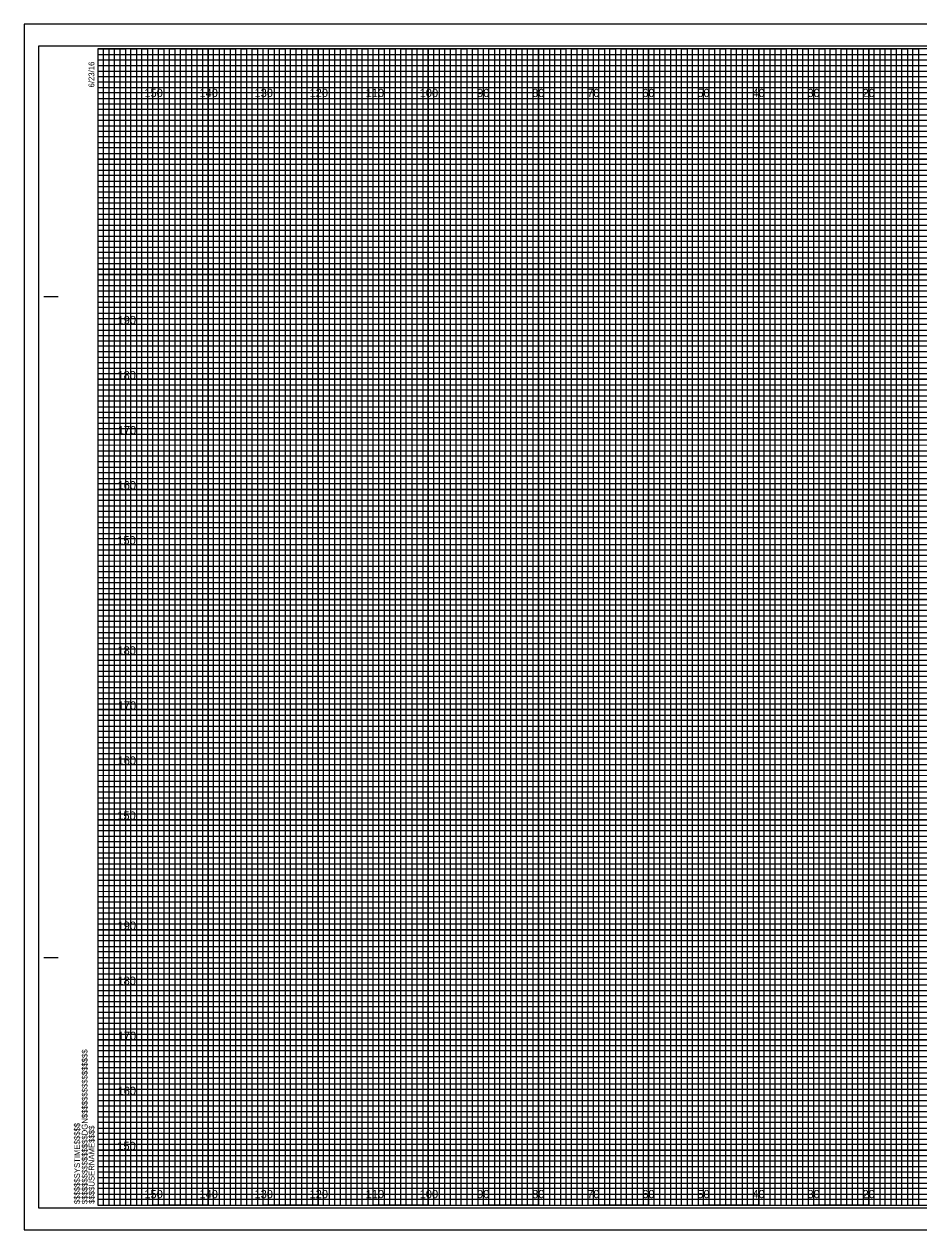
# Model space of a CAD drawing. Extents: x -13 to 323, y -5 to 434.
# Drawn here: x -13.4 to 149.1, y 215.5 to 434.5 of the extents above; entities that cross this region are included whole.
import ezdxf

# ---------------------------------------------------------------- set-up
doc = ezdxf.new("R2010")
doc.units = 0
for name, color, linetype in [('Exist Cross Section Cell', 7, 'Continuous'), ('Exist XS Center Line Elevation Label', 7, 'Continuous'), ('Exist XS Ground Line', 7, 'Continuous'), ('Prop CMT Pvmt Course 1', 7, 'Continuous'), ('Prop CMT Pvmt Course 2', 7, 'Continuous'), ('Prop CMT Pvmt Course 3', 7, 'Continuous'), ('Prop CMT Shld Paved Course 1', 7, 'Continuous'), ('Prop CMT Shld Paved Course 2', 7, 'Continuous'), ('Prop CMT Subgrade Earthwork', 7, 'Continuous'), ('Prop XS Ditch Standard Text', 7, 'Continuous'), ('Scratch_Level_0', 7, 'Continuous')]:
    doc.layers.add(name, color=color, linetype=linetype)

msp = doc.modelspace()

# ---------------------------------------------------------------- linework, layer by layer
at = {"layer": 'Exist XS Center Line Elevation Label'}
for points in [[(0, 430), (5, 430), (5, 220), (15, 220), (15, 430), (25, 430), (25, 220), (35, 220), (35, 430), (45, 430), (45, 220), (55, 220), (55, 430), (65, 430), (65, 220), (75, 220), (75, 430), (85, 430), (85, 220), (95, 220), (95, 430), (105, 430), (105, 220), (115, 220), (115, 430), (125, 430), (125, 220), (135, 220), (135, 430), (145, 430), (145, 220), (155, 220)], [(0, 425), (275, 425)], [(0, 405), (320, 405), (320, 415), (0, 415)], [(0, 385), (320, 385), (320, 395), (0, 395)], [(0, 365), (320, 365), (320, 375), (0, 375)], [(0, 345), (320, 345), (320, 355), (0, 355)], [(0, 325), (320, 325), (320, 335), (0, 335)], [(0, 305), (320, 305), (320, 315), (0, 315)], [(0, 285), (320, 285), (320, 295), (0, 295)], [(0, 265), (320, 265), (320, 275), (0, 275)], [(0, 245), (320, 245), (320, 255), (0, 255)], [(0, 225), (320, 225), (320, 235), (0, 235)]]:
    msp.add_lwpolyline(points, dxfattribs=at)
at = {"layer": 'Exist XS Ground Line'}
for p, q in [((10, 430), (0, 430)), ((10, 220), (10, 430)), ((30, 430), (20, 430)), ((20, 430), (20, 220)), ((30, 220), (30, 430)), ((50, 430), (40, 430)), ((40, 430), (40, 220)), ((50, 220), (50, 430)), ((70, 430), (60, 430)), ((60, 430), (60, 220)), ((70, 220), (70, 430)), ((90, 430), (80, 430)), ((80, 430), (80, 220)), ((90, 220), (90, 430)), ((110, 430), (100, 430)), ((100, 430), (100, 220)), ((110, 220), (110, 430)), ((130, 430), (120, 430)), ((120, 430), (120, 220)), ((130, 220), (130, 430)), ((150, 430), (140, 430)), ((140, 430), (140, 220)), ((20, 220), (10, 220)), ((40, 220), (30, 220)), ((60, 220), (50, 220)), ((80, 220), (70, 220)), ((100, 220), (90, 220)), ((120, 220), (110, 220)), ((140, 220), (130, 220))]:
    msp.add_line(p, q, dxfattribs=at)
for points in [[(0, 420), (320, 420), (320, 410), (0, 410)], [(0, 400), (320, 400), (320, 390), (0, 390)], [(0, 380), (320, 380), (320, 370), (0, 370)], [(0, 360), (320, 360), (320, 350), (0, 350)], [(0, 340), (320, 340), (320, 330), (0, 330)], [(0, 320), (320, 320), (320, 310), (0, 310)], [(0, 300), (320, 300), (320, 290), (0, 290)], [(0, 280), (320, 280), (320, 270), (0, 270)], [(0, 260), (320, 260), (320, 250), (0, 250)], [(0, 240), (320, 240), (320, 230), (0, 230)]]:
    msp.add_lwpolyline(points, dxfattribs=at)
at = {"layer": 'Prop CMT Pvmt Course 1'}
for p, q in [((323.3, 434.5), (-13.4, 434.5)), ((-13.4, 434.5), (-13.4, 215.5)), ((-13.4, 215.5), (323.3, 215.5))]:
    msp.add_line(p, q, dxfattribs=at)
at = {"layer": 'Prop CMT Pvmt Course 2'}
msp.add_lwpolyline([(-13.4, 215.5), (323.3, 215.5), (323.3, 434.5), (-13.4, 434.5)], close=True, dxfattribs=at)
at = {"layer": 'Prop CMT Pvmt Course 3'}
msp.add_lwpolyline([(-10.8, 219.5), (322.4, 219.5), (322.4, 430.5), (-10.8, 430.5)], close=True, dxfattribs=at)
at = {"layer": 'Prop CMT Shld Paved Course 1'}
for p, q in [((-9.8, 385), (-7.3, 385)), ((-9.7, 385), (-7.2, 385)), ((-9.8, 265), (-7.3, 265)), ((-9.7, 265), (-7.2, 265)), ((0, 220), (0, 220)), ((0, 220), (0, 220)), ((0, 220), (0, 220)), ((0, 220), (0, 220)), ((0, 220), (0, 220)), ((0, 220), (0, 220)), ((0, 220), (0, 220))]:
    msp.add_line(p, q, dxfattribs=at)
msp.add_lwpolyline([(320, 430), (0, 430), (0, 220), (320, 220)], close=True, dxfattribs=at)
at = {"layer": 'Prop CMT Shld Paved Course 2'}
for points in [[(0, 220), (1, 220), (1, 430), (2, 430), (2, 220)], [(2, 220), (3, 220), (3, 430), (4, 430), (4, 220)], [(5, 220), (6, 220), (6, 430), (7, 430), (7, 220)], [(7, 220), (8, 220), (8, 430), (9, 430), (9, 220)], [(10, 220), (11, 220), (11, 430), (12, 430), (12, 220)], [(12, 220), (13, 220), (13, 430), (14, 430), (14, 220)], [(15, 220), (16, 220), (16, 430), (17, 430), (17, 220)], [(17, 220), (18, 220), (18, 430), (19, 430), (19, 220)], [(20, 220), (21, 220), (21, 430), (22, 430), (22, 220)], [(22, 220), (23, 220), (23, 430), (24, 430), (24, 220)], [(25, 220), (26, 220), (26, 430), (27, 430), (27, 220)], [(27, 220), (28, 220), (28, 430), (29, 430), (29, 220)], [(30, 220), (31, 220), (31, 430), (32, 430), (32, 220)], [(32, 220), (33, 220), (33, 430), (34, 430), (34, 220)], [(35, 220), (36, 220), (36, 430), (37, 430), (37, 220)], [(37, 220), (38, 220), (38, 430), (39, 430), (39, 220)], [(40, 220), (41, 220), (41, 430), (42, 430), (42, 220)], [(42, 220), (43, 220), (43, 430), (44, 430), (44, 220)], [(45, 220), (46, 220), (46, 430), (47, 430), (47, 220)], [(47, 220), (48, 220), (48, 430), (49, 430), (49, 220)], [(50, 220), (51, 220), (51, 430), (52, 430), (52, 220)], [(52, 220), (53, 220), (53, 430), (54, 430), (54, 220)], [(55, 220), (56, 220), (56, 430), (57, 430), (57, 220)], [(57, 220), (58, 220), (58, 430), (59, 430), (59, 220)], [(60, 220), (61, 220), (61, 430), (62, 430), (62, 220)], [(62, 220), (63, 220), (63, 430), (64, 430), (64, 220)], [(65, 220), (66, 220), (66, 430), (67, 430), (67, 220)], [(67, 220), (68, 220), (68, 430), (69, 430), (69, 220)], [(70, 220), (71, 220), (71, 430), (72, 430), (72, 220)], [(72, 220), (73, 220), (73, 430), (74, 430), (74, 220)], [(75, 220), (76, 220), (76, 430), (77, 430), (77, 220)], [(77, 220), (78, 220), (78, 430), (79, 430), (79, 220)], [(80, 220), (81, 220), (81, 430), (82, 430), (82, 220)], [(82, 220), (83, 220), (83, 430), (84, 430), (84, 220)], [(85, 220), (86, 220), (86, 430), (87, 430), (87, 220)], [(87, 220), (88, 220), (88, 430), (89, 430), (89, 220)], [(90, 220), (91, 220), (91, 430), (92, 430), (92, 220)], [(92, 220), (93, 220), (93, 430), (94, 430), (94, 220)], [(95, 220), (96, 220), (96, 430), (97, 430), (97, 220)], [(97, 220), (98, 220), (98, 430), (99, 430), (99, 220)], [(100, 220), (101, 220), (101, 430), (102, 430), (102, 220)], [(102, 220), (103, 220), (103, 430), (104, 430), (104, 220)], [(105, 220), (106, 220), (106, 430), (107, 430), (107, 220)], [(107, 220), (108, 220), (108, 430), (109, 430), (109, 220)], [(110, 220), (111, 220), (111, 430), (112, 430), (112, 220)], [(112, 220), (113, 220), (113, 430), (114, 430), (114, 220)], [(115, 220), (116, 220), (116, 430), (117, 430), (117, 220)], [(117, 220), (118, 220), (118, 430), (119, 430), (119, 220)], [(120, 220), (121, 220), (121, 430), (122, 430), (122, 220)], [(122, 220), (123, 220), (123, 430), (124, 430), (124, 220)], [(125, 220), (126, 220), (126, 430), (127, 430), (127, 220)], [(127, 220), (128, 220), (128, 430), (129, 430), (129, 220)], [(130, 220), (131, 220), (131, 430), (132, 430), (132, 220)], [(132, 220), (133, 220), (133, 430), (134, 430), (134, 220)], [(135, 220), (136, 220), (136, 430), (137, 430), (137, 220)], [(137, 220), (138, 220), (138, 430), (139, 430), (139, 220)], [(140, 220), (141, 220), (141, 430), (142, 430), (142, 220)], [(142, 220), (143, 220), (143, 430), (144, 430), (144, 220)], [(145, 220), (146, 220), (146, 430), (147, 430), (147, 220)], [(147, 220), (148, 220), (148, 430), (149, 430), (149, 220)]]:
    msp.add_lwpolyline(points, dxfattribs=at)
at = {"layer": 'Prop CMT Subgrade Earthwork'}
for p, q in [((10, 220), (10, 430)), ((20, 220), (20, 430)), ((30, 220), (30, 430)), ((40, 220), (40, 430)), ((50, 220), (50, 430)), ((60, 220), (60, 430)), ((70, 220), (70, 430)), ((80, 220), (80, 430)), ((90, 220), (90, 430)), ((100, 220), (100, 430)), ((110, 220), (110, 430)), ((120, 220), (120, 430)), ((130, 220), (130, 430)), ((140, 220), (140, 430)), ((0, 420), (320, 420)), ((0, 410), (320, 410)), ((0, 400), (320, 400)), ((0, 390), (320, 390)), ((0, 380), (320, 380)), ((0, 370), (320, 370)), ((0, 360), (320, 360)), ((0, 350), (320, 350)), ((0, 340), (320, 340)), ((0, 330), (320, 330)), ((0, 320), (320, 320)), ((0, 310), (320, 310)), ((0, 300), (320, 300)), ((0, 290), (320, 290)), ((0, 280), (320, 280)), ((0, 270), (320, 270)), ((0, 260), (320, 260)), ((0, 250), (320, 250)), ((0, 240), (320, 240)), ((0, 230), (320, 230))]:
    msp.add_line(p, q, dxfattribs=at)
at = {"layer": 'Scratch_Level_0'}
for p, q in [((0, 429), (260, 429)), ((260, 427.98), (0, 427.98)), ((0, 427.98), (0, 427)), ((0, 427), (260, 427)), ((260, 425.89), (0, 425.89)), ((0, 425.89), (0, 424)), ((0, 424), (320, 424))]:
    msp.add_line(p, q, dxfattribs=at)
for points in [[(0, 423), (270, 423), (320, 423), (320, 422), (0, 422)], [(0, 421), (320, 421), (320, 419), (0, 419)], [(0, 418), (320, 418), (320, 417), (0, 416.98)], [(0, 416), (320, 416), (320, 414), (0, 414)], [(0, 413), (320, 413), (320, 412), (0, 412)], [(0, 411), (320, 411), (320, 409), (0, 409)], [(0, 408), (320, 408), (320, 407), (0, 407)], [(0, 406), (320, 406), (320, 404), (0, 404)], [(0, 403), (320, 403), (320, 402), (0, 402)], [(0, 401), (320, 401), (320, 399), (0, 399)], [(0, 398), (320, 398), (320, 397), (0, 397)], [(0, 396), (320, 396), (320, 393.95), (320, 393), (320, 392), (0, 392)], [(0, 394), (320, 394), (320, 393), (0, 393)], [(0, 391), (320, 391), (320, 389), (0, 389.03)], [(0, 389.03), (320, 389), (320, 388), (0, 388)], [(0, 387), (320, 387), (320, 386), (0, 386)], [(0, 384), (320, 384), (320, 383), (0, 383)], [(0, 382), (320, 382), (320, 381), (0, 381)], [(-0.07, 378.89), (320, 378.89), (320, 377.88), (-0.07, 377.88)], [(0, 377), (320, 377), (320, 376), (0, 376)], [(0, 374), (320, 374), (320, 373), (0, 373)], [(0, 372), (320, 372), (320, 371), (0, 371)], [(0, 369), (320, 369), (320, 368), (0, 368)], [(0, 367), (320, 367), (320, 366), (0, 366)], [(0, 364), (320, 364), (320, 363), (0, 363)], [(0, 362), (320, 362), (320, 361), (0, 361)], [(0, 359), (320, 359), (319.99, 357.98), (0, 358)], [(0, 357), (320, 357), (320, 356), (0, 356)], [(0, 354), (320, 354), (320, 353), (0, 353)], [(0, 352), (320, 352), (320, 351), (0, 351)], [(0, 349), (320, 349), (320, 348), (0, 348)], [(0, 347), (320, 347), (320, 346), (0, 346)], [(0, 344), (320, 344), (320, 343), (0, 343)], [(0, 342), (320, 342), (320, 341), (0, 341)], [(0, 339), (320, 339), (320, 338), (0, 338)], [(0, 336.99), (320.07, 336.91), (320, 336), (0, 336)], [(0, 334), (320, 334), (320, 333), (0, 333)], [(0, 332), (320, 332), (320, 331), (0, 331)], [(0, 329), (320, 329), (320, 328), (0, 328)], [(0, 327), (320, 327), (320, 326), (0, 326)], [(0, 324), (320, 324), (320, 323), (0, 323)], [(0, 322), (320, 322), (320, 321), (0, 321)], [(0, 319), (320, 319), (320, 318), (0, 318)], [(0, 317), (320, 317), (320, 316), (0, 316)], [(0, 314), (320, 314), (320, 313), (0, 313)], [(0, 312), (320, 312), (320, 311), (0, 311)], [(0, 309), (320, 309), (320, 308), (0, 308)], [(0, 307), (320, 307), (320, 306), (0, 306)], [(0, 304), (320, 304), (320, 303), (0, 303)], [(0, 302), (320, 302), (320, 301), (0, 301)], [(0, 299), (320, 299), (319.99, 297.98), (0, 298)], [(0, 297), (320, 297), (320, 296), (0, 296)], [(0, 294), (320, 294), (320, 293), (0, 293)], [(0, 292), (320, 292), (320, 291), (0, 291)], [(0, 289), (320, 289), (320, 288), (0, 288)], [(0, 287), (320, 287), (320, 286), (0, 286)], [(0, 284), (320, 284), (320, 283), (0, 283)], [(0, 282), (320, 282), (320, 281), (0, 281)], [(0, 279), (320, 279), (320, 278), (0, 278)], [(0, 276.99), (320.07, 276.91), (320, 276), (0, 276)], [(0, 274), (320, 274), (320, 273), (0, 273)], [(0, 272), (320, 272), (320, 271), (0, 271)], [(0, 269), (320, 269), (320, 268), (0, 268)], [(0, 267), (320, 267), (320, 266), (0, 266)], [(0, 264), (320, 264), (320, 263), (0, 263)], [(0, 262), (320, 262), (320, 261), (0, 261)], [(0, 259), (320, 259), (320, 258), (0, 258)], [(0, 257), (320, 257), (320, 256), (0, 256)], [(0, 254), (320, 254), (320, 253), (0, 253)], [(0, 252), (320, 252), (320, 251), (0, 251)], [(0, 249), (320, 249), (320, 248), (0, 248)], [(0, 247), (320, 247), (320, 246), (0, 246)], [(0, 244), (320, 244), (320, 243), (0, 243)], [(0, 242), (320, 242), (320, 241), (0, 241)], [(0, 239), (320, 239), (320, 238), (0, 238)], [(0, 237), (320, 237), (320, 236), (0, 236)], [(0, 234), (320, 234), (320, 233), (0, 233)], [(0, 232), (320, 232), (320, 231), (0, 231)], [(0, 229), (320, 229), (320, 228), (0, 228)], [(0, 227), (320, 227), (320, 226), (0, 226)], [(0, 224), (320, 224), (320, 223), (0, 223)], [(0, 222), (320, 222), (320, 221), (0, 221)]]:
    msp.add_lwpolyline(points, dxfattribs=at)

# ---------------------------------------------------------------- texts
at = {"layer": 'Exist Cross Section Cell'}
for s, p in [('190', (3.57, 380)), ('180', (3.55, 370)), ('170', (3.61, 360)), ('160', (3.57, 350)), ('150', (3.52, 340)), ('180', (3.55, 320)), ('170', (3.61, 310)), ('160', (3.57, 300)), ('150', (3.52, 290)), ('190', (3.57, 270)), ('180', (3.55, 260)), ('170', (3.61, 250)), ('160', (3.57, 240)), ('150', (3.52, 230))]:
    msp.add_text(s, height=1.5, dxfattribs=at).set_placement(p)
at = {"layer": 'Prop CMT Shld Paved Course 1'}
for s, p in [('6/23/16', (-0.65, 423)), ('$$$$$$$$$$$$$$$$DGN$$$$$$$$$$$$$$$$', (-1.88, 220.18)), ('$$$$$$SYSTIME$$$$$', (-3.26, 220.18)), ('$$$$USERNAME$$$$', (-0.62, 220.23))]:
    msp.add_text(s, height=1.05, rotation=90, dxfattribs=at).set_placement(p)
at = {"layer": 'Prop XS Ditch Standard Text'}
for s, p in [('150', (8.44, 421.25)), ('140', (18.44, 421.25)), ('130', (28.44, 421.25)), ('120', (38.44, 421.25)), ('110', (48.62, 421.25)), ('100', (58.44, 421.25)), ('90', (68.86, 421.25)), ('80', (78.86, 421.25)), ('70', (88.86, 421.25)), ('60', (98.86, 421.25)), ('50', (108.86, 421.25)), ('40', (118.86, 421.25)), ('30', (128.86, 421.25)), ('20', (138.86, 421.25)), ('150', (8.44, 221.25)), ('140', (18.44, 221.25)), ('130', (28.44, 221.25)), ('120', (38.44, 221.25)), ('110', (48.62, 221.25)), ('100', (58.44, 221.25)), ('90', (68.86, 221.25)), ('80', (78.86, 221.25)), ('70', (88.86, 221.25)), ('60', (98.86, 221.25)), ('50', (108.86, 221.25)), ('40', (118.86, 221.25)), ('30', (128.86, 221.25)), ('20', (138.86, 221.25))]:
    msp.add_text(s, height=1.5, dxfattribs=at).set_placement(p)

doc.saveas('drawing.dxf')
